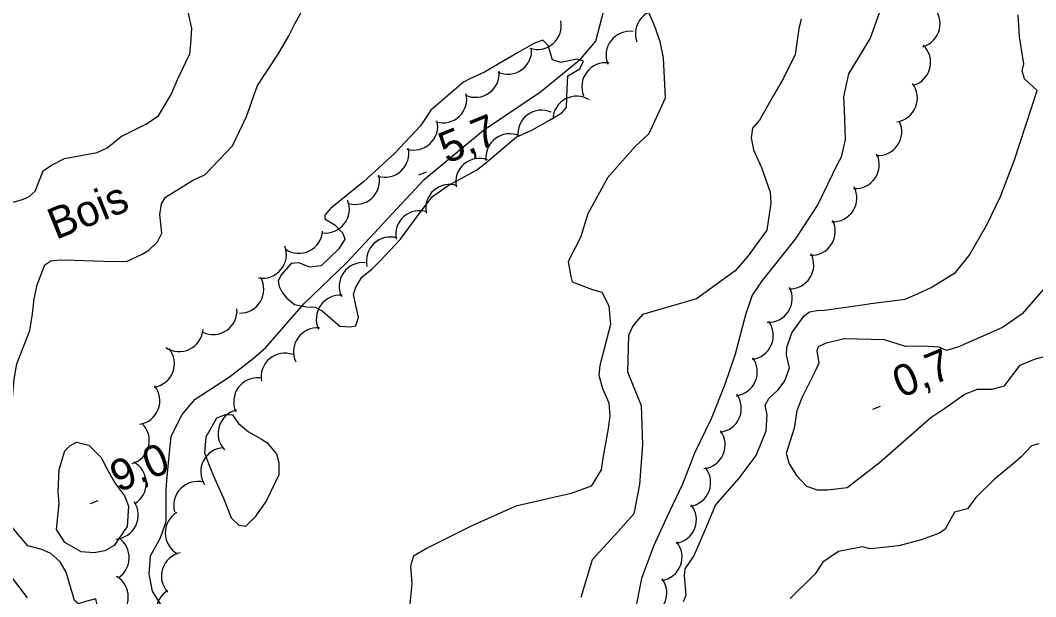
# Model space of a CAD drawing. Extents: x 362852 to 366875, y 5563573 to 5566479.
# Drawn here: x 363050.9 to 363178.5, y 5564846.1 to 5564918.5 of the extents above; entities that cross this region are included whole.
import ezdxf

# ---------------------------------------------------------------- set-up
doc = ezdxf.new("R2010")
doc.units = 0
for name, color, linetype in [('Niveau 2', 7, 'Continuous'), ('Niveau 22', 7, 'Continuous'), ('Niveau 3', 7, 'Continuous'), ('Niveau 4', 7, 'Continuous'), ('Niveau 44', 7, 'Continuous')]:
    doc.layers.add(name, color=color, linetype=linetype)

msp = doc.modelspace()

# ---------------------------------------------------------------- linework, layer by layer
at = {"layer": 'Niveau 2'}
for points in [[(363123.36, 5564927.57), (363123.33, 5564926.31), (363122.93, 5564924.14), (363123.18, 5564923.55), (363125.66, 5564923.6), (363127.33, 5564923.05), (363128.66, 5564921.67), (363129.65, 5564919.9), (363130.65, 5564917.51), (363131.24, 5564915.81)], [(363047.7, 5564895.02), (363051.18, 5564895.98), (363052.03, 5564896.33), (363052.75, 5564897.01), (363053.75, 5564899.56), (363054.83, 5564900.26), (363056.47, 5564901.13), (363060.55, 5564901.85), (363061.8, 5564902.44), (363063.58, 5564903.87), (363066.68, 5564905.42), (363068.25, 5564906.46), (363069.91, 5564909.22), (363070.68, 5564911.11), (363072.18, 5564914.24), (363072.34, 5564915.5), (363072.47, 5564917.43), (363071.51, 5564921.66)], [(363053.96, 5564887.76), (363054.75, 5564888.28), (363055.89, 5564888.38), (363057.72, 5564888.34), (363061.33, 5564888.23), (363064.22, 5564888.19), (363066.22, 5564889.09), (363067.05, 5564889.63), (363068.13, 5564890.64), (363068.67, 5564891.74), (363068.43, 5564894.08), (363068.62, 5564895.41), (363069.14, 5564896.26), (363072.67, 5564898.42), (363074.08, 5564899.08), (363075, 5564900.02), (363077.55, 5564902.72), (363079.32, 5564906.4), (363080.69, 5564910.29), (363083.3, 5564914.2), (363084.64, 5564916.51), (363085.38, 5564918.01), (363086.96, 5564920.8)], [(363159.4, 5564921.01), (363157.66, 5564916.21), (363154.95, 5564911.75), (363154.35, 5564908.86), (363154.42, 5564907.2), (363154.54, 5564903.49), (363154.03, 5564901.27), (363153.53, 5564900.37), (363151.12, 5564895.35), (363148.24, 5564891), (363144.09, 5564885.81), (363142.86, 5564883.98), (363142.02, 5564881.49), (363140.71, 5564876.55), (363139.42, 5564872.75), (363137.71, 5564868.46), (363135.59, 5564864.12), (363134.08, 5564860.23), (363132.1, 5564856.01), (363130.46, 5564852.44), (363128.95, 5564848.42), (363128.1, 5564844.18)], [(363149.02, 5564918.63), (363148.73, 5564917.38), (363148.26, 5564914.18), (363146.74, 5564911.1), (363145.58, 5564909.11), (363143.79, 5564905.91), (363142.89, 5564904.91), (363142.71, 5564903.71), (363143.02, 5564902.21), (363144.02, 5564900), (363145.13, 5564896.9), (363145.22, 5564895.5), (363144.69, 5564892.14), (363142.35, 5564888.91), (363140.7, 5564887.03), (363135.86, 5564883.5), (363129.06, 5564881.52), (363128.3, 5564880.64), (363127.8, 5564880.05), (363127.33, 5564878.91), (363127.19, 5564874.35), (363128.9, 5564870.12), (363129.09, 5564865.19), (363128.69, 5564860.2), (363127.98, 5564856.52), (363126.02, 5564854.32), (363122.76, 5564850.76), (363121.31, 5564846.02)], [(363090.41, 5564892.8), (363091.42, 5564891.73), (363091.66, 5564891.01), (363090.93, 5564889.77), (363088.7, 5564887.65), (363087.27, 5564887.48), (363085.91, 5564888.04), (363084.95, 5564887.95), (363083.72, 5564886.56), (363083.3, 5564885.76), (363083.41, 5564885.05), (363083.76, 5564884.39), (363084.33, 5564883.62), (363085.36, 5564882.81), (363086.86, 5564882.5), (363087.94, 5564882.45), (363088.82, 5564882.01), (363091.06, 5564880.08), (363092.3, 5564879.97), (363093.06, 5564880.1), (363093.41, 5564881.19), (363093.04, 5564882.66), (363092.75, 5564884.1), (363093.07, 5564884.98), (363093.8, 5564886.22), (363095.1, 5564887.27), (363096.07, 5564888.24), (363098.66, 5564891.01), (363101.21, 5564894.46), (363102.68, 5564896.33), (363104.65, 5564897.72), (363108.22, 5564899.65), (363109.39, 5564900.58), (363113.22, 5564903.81), (363115.16, 5564904.69), (363117.39, 5564905.94), (363118.95, 5564906.84), (363119.53, 5564907.53), (363119.61, 5564909.87), (363119.69, 5564911.47), (363121.2, 5564912.35), (363121.65, 5564913.35), (363120.86, 5564913.58), (363118.8, 5564913.15), (363117.78, 5564913.48), (363117.21, 5564915.3), (363116.55, 5564915.96), (363115.42, 5564915.55), (363113.35, 5564914.37), (363109.24, 5564911.96), (363107.4, 5564911.12), (363106.57, 5564910.71), (363102.49, 5564907.19), (363101.2, 5564905.21), (363097.95, 5564901.78), (363094.02, 5564898.19), (363089.87, 5564894.83), (363089.14, 5564894.02), (363089.16, 5564893.53), (363090.41, 5564892.8), (363090.41, 5564892.8)], [(363131.24, 5564915.81), (363131.67, 5564913.74), (363131.93, 5564908.67), (363129.86, 5564904.23), (363128.15, 5564902.64), (363124.69, 5564898.69), (363122.22, 5564894.15), (363121.27, 5564891.19), (363119.73, 5564888.17), (363120.07, 5564886.31), (363120.23, 5564885.63), (363122.68, 5564884.72), (363123.97, 5564884.32), (363124.86, 5564882.64), (363125.04, 5564880.27), (363123.7, 5564875.15), (363123.59, 5564873.91), (363124.05, 5564872.23), (363124.86, 5564870.45), (363124.98, 5564868.81), (363124.78, 5564867.22), (363124.09, 5564863.5), (363123.89, 5564862.04), (363122.62, 5564860.01), (363120.13, 5564859.09), (363113.18, 5564857.48), (363107.65, 5564855.03), (363106.31, 5564854.35), (363102.01, 5564852.23), (363100.32, 5564851.21), (363100.03, 5564850.4), (363099.92, 5564849.92), (363100.09, 5564847.74), (363099.74, 5564844.4)], [(363051.84, 5564852.49), (363050.62, 5564853.91), (363049.93, 5564854.81), (363048.37, 5564857.03), (363047.66, 5564858.86), (363047.04, 5564861.54), (363047.6, 5564863.34), (363049.15, 5564864.99), (363049.78, 5564867.06), (363049.86, 5564870.6), (363050.12, 5564873.4), (363050.48, 5564875.36), (363052.1, 5564879.54), (363052.42, 5564881.61), (363052.62, 5564883.51), (363053.02, 5564885.24), (363053.96, 5564887.76)], [(363075.18, 5564861.35), (363074.58, 5564862.78), (363074.08, 5564864.13), (363074.26, 5564866.2), (363075.58, 5564868.57), (363076.72, 5564868.98), (363077.54, 5564868.95), (363078.32, 5564867.84)], [(363078.32, 5564867.84), (363079.57, 5564866.81), (363081.21, 5564865.87), (363081.88, 5564865.47), (363083.1, 5564864.04), (363083.38, 5564862.92), (363083.39, 5564861.42), (363081.78, 5564858.12), (363080.38, 5564856.1), (363079.19, 5564854.92), (363078.38, 5564855.07), (363077.43, 5564855.99), (363076.55, 5564858.24), (363075.18, 5564861.35)], [(363063.97, 5564858.76), (363064.51, 5564857.49), (363064.34, 5564854.92), (363062.71, 5564852.56), (363061.5, 5564851.86), (363060.17, 5564851.62), (363058.56, 5564851.75), (363056.5, 5564852.94), (363055.44, 5564854.56), (363055.76, 5564857.81), (363055.65, 5564859.27), (363055.78, 5564862.07), (363056.48, 5564864.42), (363057.14, 5564865.07), (363057.95, 5564865.53), (363059.49, 5564865.12), (363061.07, 5564863.6), (363061.84, 5564862.05), (363062.79, 5564860.39), (363063.1, 5564859.96), (363063.97, 5564858.76)], [(363058.7, 5564831.68), (363057.59, 5564832.4), (363057.11, 5564833.7), (363056.45, 5564836.61), (363055.75, 5564838.57), (363056.27, 5564841.04), (363057.26, 5564841.82), (363059.46, 5564842.69), (363060.34, 5564843.56), (363060.62, 5564844.67), (363060.39, 5564845.83), (363059.26, 5564845.54), (363058.2, 5564845.22), (363057.71, 5564845.64), (363056.66, 5564849.2), (363055.92, 5564850.51), (363054.75, 5564851.52), (363053.59, 5564852.04), (363051.84, 5564852.49)], [(363051.79, 5564845.96), (363048.93, 5564849.77)]]:
    msp.add_lwpolyline(points, dxfattribs=at)
at = {"layer": 'Niveau 22'}
msp.add_lwpolyline([(363068.91, 5564844.61), (363067.51, 5564846.82), (363067.07, 5564848.96), (363067.26, 5564851.24), (363068.53, 5564853.51), (363069.23, 5564855.54), (363069.21, 5564859.63), (363069.41, 5564861.64), (363069.84, 5564866.28), (363071.25, 5564868.99), (363072.87, 5564870.91), (363077.17, 5564873.72), (363080.15, 5564876.02), (363081.73, 5564877.39), (363086.55, 5564882.93), (363091.92, 5564888.07), (363101.63, 5564898.47), (363109.09, 5564904.67), (363116.26, 5564909.49), (363121.34, 5564913.61), (363123.2, 5564915.85), (363124.23, 5564919.71)], dxfattribs=at)
at = {"layer": 'Niveau 3'}
for p, q in [((363100.97, 5564899.06), (363101.93, 5564899.45)), ((363158.02, 5564869.65), (363158.98, 5564870.04)), ((363059.7, 5564857.81), (363060.66, 5564858.2))]:
    msp.add_line(p, q, dxfattribs=at)
at = {"layer": 'Niveau 4'}
for points in [[(363134.22, 5564845.5), (363134.56, 5564846.33), (363134.36, 5564848.76), (363134.44, 5564849.61), (363135.53, 5564851.2), (363137.13, 5564854.88), (363138.24, 5564857.61), (363141.22, 5564861), (363143.35, 5564863.84), (363144.62, 5564866.95), (363144.73, 5564868.94), (363144.47, 5564870.15), (363144.94, 5564870.98), (363146.1, 5564872.09), (363146.96, 5564873.21), (363147.53, 5564874.83), (363147.15, 5564876.49), (363147.21, 5564877.4), (363147.82, 5564879.22), (363149.37, 5564881.38), (363150.05, 5564881.85), (363151.04, 5564882.02), (363151.96, 5564882.09), (363155.52, 5564882.58), (363156.7, 5564882.76), (363157.77, 5564882.9), (363162.07, 5564883.44), (363163.7, 5564884.19), (363165.33, 5564884.94), (363168.39, 5564886.79), (363170.12, 5564888.96), (363172.34, 5564892.78), (363174.06, 5564896.33), (363175.82, 5564900.96), (363178.65, 5564909.63), (363177.08, 5564911.11), (363176.79, 5564912.11), (363176.98, 5564913.01), (363176.44, 5564916.37), (363176.29, 5564919.13)], [(363180.03, 5564885.39), (363176.77, 5564881.64), (363174.3, 5564879.91), (363168.68, 5564877.42), (363167.28, 5564877.02), (363166.34, 5564877.45), (363164.22, 5564877.56), (363162.12, 5564877.5), (363159.5, 5564878.34), (363154.42, 5564878.47), (363152.02, 5564877.91), (363151.13, 5564877.47), (363150.97, 5564876.96), (363151.23, 5564875.44), (363150.81, 5564874.51), (363150.24, 5564873.33), (363149.1, 5564871.09), (363148.47, 5564869.45), (363148.12, 5564867.29), (363147.13, 5564864.11), (363147.49, 5564862.81), (363148.43, 5564861.32), (363149.69, 5564859.97), (363151.01, 5564859.52), (363152.33, 5564859.51), (363154.77, 5564859.84), (363158.87, 5564862.94), (363165.29, 5564868.59), (363167.06, 5564869.77), (363169.48, 5564871.48), (363171.14, 5564872.17), (363173.03, 5564872.15), (363174.54, 5564872.59), (363176.53, 5564875.19), (363178.34, 5564875.95), (363182.86, 5564877.16)], [(363178.86, 5564865.3), (363177.96, 5564865.05), (363176.65, 5564863.68), (363175.69, 5564862.84), (363173.27, 5564860.82), (363170.94, 5564858.58), (363169.91, 5564857.14), (363168.27, 5564856.71), (363167.09, 5564854.58), (363166.41, 5564854.11), (363164.07, 5564853.25), (363161.3, 5564852.52), (363157.69, 5564852.14), (363156.72, 5564852.36), (363153.69, 5564851.78), (363151.74, 5564850.46), (363150.78, 5564848.99), (363147.62, 5564845.9)]]:
    msp.add_lwpolyline(points, dxfattribs=at)
at = {"layer": 'Niveau 44'}
for centre, start, end in [((363163.47, 5564918.03), 286.1728, 46.1507), ((363131.18, 5564916.77), 79.3406, 199.3186), ((363115.87, 5564917.8), 251.1579, 11.1358), ((363127.5, 5564914.09), 82.3648, 202.3428), ((363112.15, 5564914.69), 245.4753, 5.4533), ((363162.28, 5564913.18), 286.1728, 46.1507), ((363124.45, 5564910.13), 82.3648, 202.3428), ((363108.08, 5564911.79), 245.4753, 5.4533), ((363160.61, 5564908.7), 277.7911, 37.7691), ((363103.99, 5564908.59), 253.2718, 13.2498), ((363120.8, 5564905.93), 57.7696, 177.7476), ((363116.4, 5564904.19), 66.5364, 186.5144), ((363100.34, 5564905.17), 253.2718, 13.2498), ((363158.65, 5564904.47), 265.6826, 25.6605), ((363112.38, 5564901.22), 66.5364, 186.5144), ((363096.71, 5564901.76), 252.8695, 12.8475), ((363108.6, 5564898.13), 70.9506, 190.9285), ((363155.83, 5564900.34), 265.6826, 25.6605), ((363093.04, 5564898.35), 252.8695, 12.8475), ((363104.83, 5564894.85), 71.1003, 191.0783), ((363153, 5564896.17), 267.3181, 27.296), ((363089.24, 5564894.76), 261.958, 21.9359), ((363101.06, 5564891.57), 71.1003, 191.0783), ((363150.3, 5564891.97), 267.3181, 27.296), ((363085.89, 5564892.21), 236.1712, 356.1492), ((363097.38, 5564888.26), 73.1444, 193.1223), ((363081.33, 5564889.08), 260.4826, 20.4606), ((363147.59, 5564887.76), 267.3181, 27.296), ((363093.96, 5564885.05), 85.0104, 204.9883), ((363078.49, 5564884.71), 269.0576, 29.0355), ((363144.89, 5564883.55), 267.3181, 27.296), ((363091.09, 5564880.96), 85.0104, 204.9883), ((363075.13, 5564882.02), 244.4117, 4.3896), ((363142.51, 5564878.9), 276.2638, 36.2417), ((363070.87, 5564879.88), 235.7766, 355.7546), ((363088.22, 5564876.86), 85.0104, 204.9883), ((363067.26, 5564875.38), 278.6769, 38.6549), ((363084.14, 5564873.68), 70.0276, 190.0055), ((363140.5, 5564874.33), 276.2638, 36.2417), ((363080.71, 5564870.59), 83.8523, 203.8302), ((363065.44, 5564870.72), 278.6769, 38.6549), ((363138.49, 5564869.75), 276.2638, 36.2417), ((363078.74, 5564866.61), 102.9396, 222.9175), ((363064.11, 5564865.7), 286.4734, 46.4513), ((363136.47, 5564865.18), 276.2638, 36.2417), ((363076.57, 5564861.82), 92.4791, 212.457), ((363063.73, 5564860.36), 301.4848, 61.4627), ((363134.64, 5564860.45), 278.9148, 38.8928), ((363073.18, 5564857.58), 75.3022, 195.2801), ((363062.72, 5564856.35), 273.5882, 33.5661), ((363132.84, 5564855.78), 278.9148, 38.8928), ((363072.11, 5564854.12), 121.029, 241.0069), ((363061.58, 5564851.02), 304.1369, 53.0565), ((363131.04, 5564851.12), 278.9148, 38.8928), ((363071.63, 5564848.71), 102.2449, 222.2229), ((363061.47, 5564846.07), 299.9005, 59.8784), ((363129.13, 5564846.58), 276.2216, 36.1995), ((363070.97, 5564844.33), 121.4185, 241.3965)]:
    msp.add_arc(centre, 3, start, end, dxfattribs=at)

# ---------------------------------------------------------------- texts
at = {"layer": 'Niveau 3'}
for s, p in [('5,7  ', (363104.48, 5564900.42)), ('0,7  ', (363161.53, 5564871.01)), ('9,0  ', (363063.21, 5564859.17))]:
    msp.add_text(s, height=3.93, rotation=22.09, dxfattribs=at).set_placement(p)
at = {"layer": 'Niveau 44'}
msp.add_text('Bois', height=3.93, rotation=22.09, dxfattribs=at).set_placement((363055.37, 5564890.88))

doc.saveas('drawing.dxf')
